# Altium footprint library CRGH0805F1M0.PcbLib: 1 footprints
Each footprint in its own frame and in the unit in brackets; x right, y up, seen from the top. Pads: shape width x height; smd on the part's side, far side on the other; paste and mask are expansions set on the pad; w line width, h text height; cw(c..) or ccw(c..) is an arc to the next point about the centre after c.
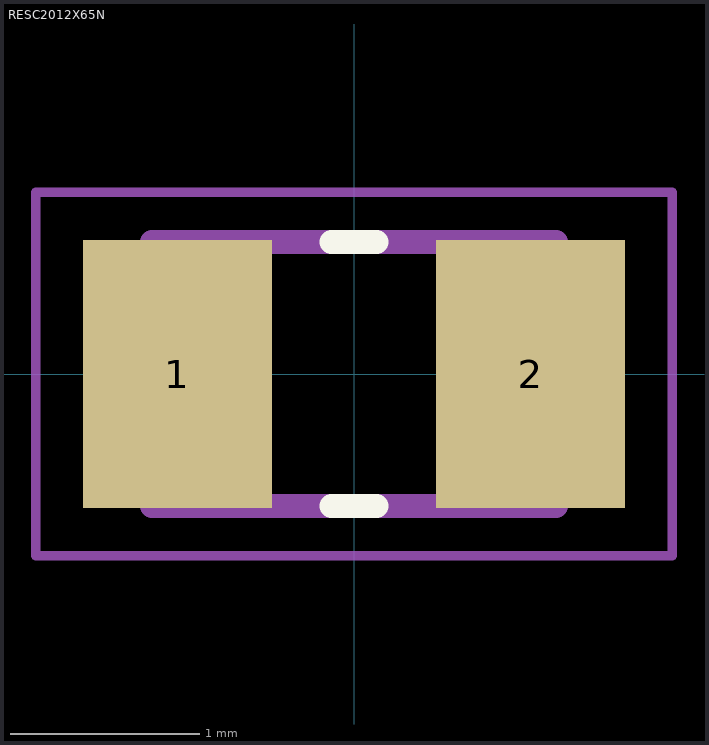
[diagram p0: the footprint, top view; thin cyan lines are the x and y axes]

## RESC2012X65N [mm]
pads (2):
  rect 1x1.42 smd: 1(-0.935,0) 2(0.935,0)
Top Overlay:
  lines w0.127: -0.12,-0.7 0.12,-0.7 ; -0.12,0.7 0.12,0.7
Mechanical 13:
  lines w0.127: -1.07,-0.7 1.07,-0.7 1.07,0.7 -1.07,0.7 -1.07,-0.7
Mechanical 15:
  lines w0.05: -1.685,-0.962 1.685,-0.962 1.685,0.962 -1.685,0.962 -1.685,-0.962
